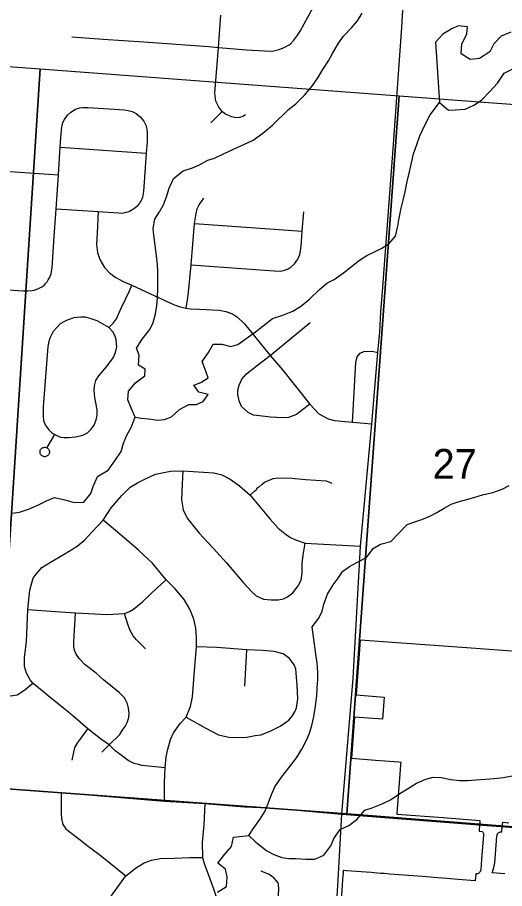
# Model space of a CAD drawing. Extents: x 0 to 34, y 0 to 26.1.
# Drawn here: x 26.652 to 27.339, y 15.919 to 17.147 of the extents above; entities that cross this region are included whole.
import ezdxf

# ---------------------------------------------------------------- set-up
doc = ezdxf.new("R2010")
doc.units = 0
for name, color, linetype in [('GM_X_County_Road', 7, 'Continuous'), ('GM_X_Minor_Lake', 7, 'Continuous'), ('GM_X_Minor_River', 7, 'Continuous'), ('GM_X_Section', 7, 'Continuous'), ('GM_X_Section_Text', 7, 'Continuous'), ('GM_X_Township_Road', 7, 'Continuous'), ('SC_Scratch1', 7, 'Continuous')]:
    doc.layers.add(name, color=color, linetype=linetype)

msp = doc.modelspace()

# ---------------------------------------------------------------- linework, layer by layer
at = {"layer": 'GM_X_County_Road'}
for points in [[(27.0981, 15.8354), (27.1037, 15.9232), (27.1095, 16.024), (27.1253, 16.2152), (27.136, 16.402), (27.1519, 16.5743), (27.1604, 16.6746), (27.1631, 16.7041), (27.1645, 16.7321), (27.1669, 16.7607), (27.1823, 16.9679), (27.1942, 17.1333), (27.1967, 17.1739), (27.2024, 17.2543), (27.2067, 17.3105), (27.2105, 17.3599), (27.2149, 17.4267), (27.2235, 17.5489)], [(25.6593, 16.1329), (25.6738, 16.1311), (25.7938, 16.1231), (25.9933, 16.107), (26.0793, 16.1018), (26.1222, 16.0984), (26.2747, 16.0857), (26.4019, 16.0766), (26.714, 16.0547), (26.8597, 16.0424), (26.9166, 16.0392), (26.9722, 16.0347), (26.9948, 16.0336), (27.0202, 16.032), (27.0574, 16.0287), (27.1095, 16.024), (27.2972, 16.0095), (27.3012, 16.0092)], [(27.3012, 16.0092), (27.3465, 16.0057), (27.3516, 16.0054)]]:
    msp.add_lwpolyline(points, dxfattribs=at)
at = {"layer": 'GM_X_Minor_Lake'}
for points in [[(27.348, 17.1264), (27.3343, 17.1205), (27.3239, 17.1096), (27.3181, 17.0987), (27.3036, 17.0893), (27.2904, 17.0879), (27.2776, 17.0957), (27.2788, 17.1093), (27.2858, 17.1237), (27.2867, 17.1339), (27.2734, 17.1352), (27.2639, 17.1304), (27.2517, 17.1233), (27.2418, 17.112)], [(27.2418, 17.112), (27.2473, 17.0269)], [(27.2473, 17.0269), (27.2597, 17.0165), (27.2695, 17.0168), (27.2835, 17.0178), (27.2957, 17.0234), (27.3064, 17.0305), (27.3183, 17.0425), (27.329, 17.0545), (27.3383, 17.0685), (27.3504, 17.0744)]]:
    msp.add_lwpolyline(points, dxfattribs=at)
at = {"layer": 'GM_X_Minor_River'}
for points in [[(26.9846, 16.9742), (26.9983, 16.9839), (27.0117, 16.9952), (27.0343, 17.0174), (27.0446, 17.0252), (27.0568, 17.0376), (27.0672, 17.0497), (27.0757, 17.0617), (27.083, 17.0734), (27.0907, 17.0858), (27.0965, 17.0964), (27.105, 17.1108), (27.1119, 17.1205), (27.123, 17.1322), (27.1315, 17.1424), (27.138, 17.1529)], [(26.9877, 16.7039), (26.9988, 16.7126), (27.0118, 16.7227), (27.0262, 16.7275), (27.0407, 16.733), (27.0514, 16.7397), (27.064, 16.7498), (27.0781, 16.7637), (27.0885, 16.7723), (27.0987, 16.7779), (27.1117, 16.7873), (27.1232, 16.7959), (27.1346, 16.8049), (27.1446, 16.8116), (27.1548, 16.8164), (27.1659, 16.8216), (27.1758, 16.828), (27.1854, 16.8389), (27.1886, 16.8529), (27.1906, 16.8643), (27.193, 16.8783), (27.1958, 16.8897), (27.1986, 16.9014), (27.2018, 16.9158), (27.2045, 16.9275), (27.2069, 16.9377), (27.2105, 16.9548), (27.2152, 16.968), (27.2195, 16.9801), (27.2265, 16.9952), (27.2342, 17.0096), (27.2473, 17.0269)], [(26.8489, 16.7409), (26.8495, 16.7515), (26.8501, 16.7659), (26.8504, 16.7887), (26.8498, 16.799), (26.8484, 16.8111), (26.8464, 16.8256), (26.8447, 16.84), (26.8437, 16.8495), (26.8461, 16.8628), (26.8523, 16.8729), (26.8582, 16.8831), (26.8625, 16.8941), (26.8661, 16.9062), (26.8723, 16.9201), (26.8857, 16.9309), (26.899, 16.9349), (26.9089, 16.9393), (26.9207, 16.946), (26.9302, 16.9485), (26.9436, 16.9552), (26.9846, 16.9742)], [(26.6442, 16.4484), (26.6552, 16.4498), (26.6693, 16.4545), (26.683, 16.4604), (26.6933, 16.4656), (26.7047, 16.4704), (26.719, 16.4671), (26.7322, 16.4632), (26.7459, 16.4641), (26.7559, 16.4761), (26.759, 16.4859), (26.7653, 16.4999), (26.7802, 16.5088), (26.7894, 16.5223), (26.7983, 16.5355), (26.8019, 16.5468), (26.8066, 16.5585), (26.8128, 16.5691), (26.818, 16.5838), (26.8121, 16.5979), (26.8081, 16.6082), (26.8086, 16.6204), (26.8186, 16.632), (26.832, 16.6417), (26.8325, 16.6512), (26.8228, 16.657), (26.8237, 16.671), (26.8201, 16.6809), (26.8282, 16.6937), (26.839, 16.7073), (26.8437, 16.7171), (26.8469, 16.7295), (26.8489, 16.7409)], [(26.8179, 16.5836), (26.827, 16.5822), (26.8368, 16.5813), (26.8501, 16.5796), (26.8595, 16.5802), (26.8694, 16.5842), (26.8809, 16.5947), (26.8939, 16.6014), (26.9045, 16.6016), (26.914, 16.6056), (26.921, 16.6154), (26.9081, 16.619), (26.9011, 16.6286), (26.9106, 16.6326), (26.9209, 16.6389), (26.9162, 16.6523), (26.9125, 16.6622), (26.9218, 16.675), (26.9284, 16.6867), (26.9405, 16.6865), (26.9533, 16.6833), (26.9628, 16.6862), (26.9877, 16.7039)], [(26.9785, 15.9939), (26.9847, 16.0034), (26.9951, 16.018), (27.0009, 16.0279), (27.0059, 16.0392), (27.0106, 16.0517), (27.0149, 16.0626), (27.0245, 16.0762), (27.0349, 16.0894), (27.0456, 16.1037), (27.0534, 16.1157), (27.0599, 16.1286), (27.0638, 16.1384), (27.0673, 16.149), (27.0694, 16.1596), (27.0718, 16.1732), (27.0742, 16.191), (27.0747, 16.2024), (27.0756, 16.2134), (27.0757, 16.2237), (27.0747, 16.237), (27.073, 16.2499), (27.0695, 16.2742), (27.0677, 16.2883), (27.0769, 16.3003), (27.0816, 16.3101), (27.084, 16.32), (27.0894, 16.334), (27.0975, 16.3472), (27.1044, 16.357), (27.111, 16.3668), (27.1205, 16.3731), (27.1308, 16.3787), (27.1441, 16.3858), (27.1538, 16.3986), (27.164, 16.4045), (27.1785, 16.4086), (27.1896, 16.4198), (27.2015, 16.4322), (27.211, 16.4356), (27.2224, 16.4396), (27.2338, 16.444), (27.2437, 16.4493), (27.2536, 16.4556), (27.2635, 16.4612), (27.2734, 16.4645), (27.284, 16.4674), (27.2958, 16.4703), (27.308, 16.474), (27.3224, 16.4773), (27.3357, 16.4821), (27.3453, 16.4873)], [(26.9785, 15.9939), (26.9883, 15.9847), (27.0037, 15.9724), (27.0135, 15.9674), (27.0248, 15.9631), (27.035, 15.9615), (27.0449, 15.9617), (27.0589, 15.9608), (27.0714, 15.9607), (27.0843, 15.9666), (27.0939, 15.9798), (27.0982, 15.99), (27.1071, 16.0025), (27.1192, 16.0084), (27.1307, 16.0166), (27.1422, 16.0298), (27.1525, 16.0331), (27.1662, 16.0387), (27.1783, 16.0442), (27.1913, 16.0532), (27.202, 16.0599), (27.215, 16.0681), (27.2279, 16.0737), (27.2382, 16.0762), (27.2495, 16.0761), (27.2631, 16.0729), (27.2752, 16.0717), (27.2874, 16.0716), (27.2984, 16.0726), (27.312, 16.0736), (27.3241, 16.0746), (27.3374, 16.076), (27.3499, 16.0781)], [(26.9344, 15.9142), (26.947, 15.9224), (26.948, 15.9353), (26.9455, 15.9467), (26.9346, 15.9552), (26.9447, 15.9676), (26.9539, 15.9788), (26.9567, 15.9917), (26.9785, 15.9939)]]:
    msp.add_lwpolyline(points, dxfattribs=at)
at = {"layer": 'GM_X_Section'}
for points in [[(26.6845, 17.0747), (26.6185, 16.0611), (26.603, 16.0634), (26.1174, 16.097), (26.1914, 17.1109)], [(26.6845, 17.0747), (27.1906, 17.0366), (27.1167, 16.0245), (26.6185, 16.0611)], [(27.1906, 17.0366), (27.6883, 16.9993), (27.6154, 15.9857), (27.1167, 16.0245)], [(26.603, 16.0634), (26.6185, 16.0611), (27.1167, 16.0245), (27.6154, 15.9857), (27.5444, 14.9891), (26.5367, 15.0651)]]:
    msp.add_lwpolyline(points, close=True, dxfattribs=at)
at = {"layer": 'GM_X_Township_Road'}
for p, q in [((26.9248, 16.9986), (26.9407, 17.0142)), ((26.7125, 16.9642), (26.8336, 16.9556)), ((26.902, 16.8567), (27.0536, 16.8457)), ((27.0087, 16.6707), (27.065, 16.7173)), ((26.973, 16.2046), (26.9756, 16.2558))]:
    msp.add_line(p, q, dxfattribs=at)
for points in [[(26.729, 17.1195), (26.7731, 17.1164), (26.8304, 17.1125), (26.9223, 17.1059), (26.9355, 17.1046), (26.9752, 17.1015), (27.0092, 17.0995), (27.0137, 17.0998), (27.0214, 17.1016), (27.0294, 17.105), (27.0352, 17.1084), (27.0376, 17.1104), (27.0418, 17.1148), (27.0473, 17.1223), (27.0506, 17.1275), (27.0564, 17.1381), (27.0769, 17.1762)], [(26.9739, 17.0099), (26.97, 17.0075), (26.9655, 17.0062), (26.9599, 17.0057), (26.9547, 17.0067), (26.9498, 17.0086), (26.9444, 17.0111), (26.9407, 17.0142), (26.9361, 17.0204), (26.9319, 17.029), (26.9304, 17.0404), (26.9355, 17.1046), (26.939, 17.1503)], [(26.7125, 16.9642), (26.7135, 16.9779), (26.715, 16.9929), (26.7164, 16.9989), (26.7184, 17.0031), (26.723, 17.0094), (26.7275, 17.0136), (26.7341, 17.0176), (26.74, 17.0195), (26.7446, 17.0202), (26.7514, 17.0202), (26.8033, 17.0166), (26.8082, 17.0159), (26.8139, 17.0145), (26.8195, 17.0118), (26.8255, 17.007), (26.8303, 17.0008), (26.8332, 16.9953), (26.8347, 16.9893), (26.8352, 16.9834), (26.8349, 16.9718), (26.8336, 16.9556), (26.8301, 16.9018), (26.8297, 16.8987), (26.8291, 16.8961), (26.8284, 16.8936), (26.8274, 16.8911), (26.8266, 16.889), (26.8255, 16.8871), (26.8245, 16.8854), (26.8226, 16.883), (26.8204, 16.8807), (26.8177, 16.8782), (26.815, 16.8763), (26.8128, 16.8749), (26.8104, 16.8737), (26.8078, 16.8727), (26.805, 16.8719), (26.8019, 16.8713), (26.7984, 16.8709), (26.7945, 16.871), (26.766, 16.8729), (26.7067, 16.877)], [(26.6238, 16.764), (26.6606, 16.7619), (26.6668, 16.7617), (26.673, 16.7622), (26.6761, 16.7628), (26.682, 16.7648), (26.6874, 16.7679), (26.6898, 16.7699), (26.692, 16.772), (26.694, 16.7744), (26.6958, 16.777), (26.6973, 16.7798), (26.6985, 16.7826), (26.6996, 16.7856), (26.7013, 16.7947), (26.7041, 16.8383), (26.7067, 16.877), (26.71, 16.9252), (26.7125, 16.9642)], [(26.5768, 16.9233), (26.5883, 16.9277), (26.5994, 16.9312), (26.6086, 16.9317), (26.6286, 16.9306), (26.71, 16.9252)], [(26.8901, 16.7375), (26.893, 16.755), (26.8971, 16.7983), (26.902, 16.8567), (26.904, 16.8707), (26.9058, 16.8771), (26.9086, 16.8828), (26.9148, 16.8924)], [(26.766, 16.8729), (26.7648, 16.8432), (26.7639, 16.827), (26.7651, 16.8155), (26.7684, 16.8057), (26.7751, 16.7947), (26.7824, 16.7867), (26.7908, 16.7804), (26.8014, 16.775), (26.8133, 16.7695), (26.8712, 16.7429), (26.8758, 16.7412), (26.8818, 16.739), (26.8901, 16.7375), (26.8963, 16.7365), (26.9089, 16.7359), (26.9365, 16.7346), (26.9462, 16.7328), (26.9553, 16.7292), (26.9625, 16.7247), (26.9724, 16.7153), (27.0087, 16.6707), (27.0257, 16.6506), (27.0643, 16.6021), (27.077, 16.5884), (27.0902, 16.5814), (27.0992, 16.5789), (27.1244, 16.5766), (27.1519, 16.5743)], [(26.8971, 16.7983), (27.0141, 16.7897), (27.0226, 16.7895), (27.0271, 16.7905), (27.0339, 16.7925), (27.0383, 16.7956), (27.0427, 16.7996), (27.0476, 16.8065), (27.0504, 16.8128), (27.0517, 16.8208), (27.0525, 16.8307), (27.0536, 16.8457), (27.0558, 16.8732)], [(26.7812, 16.7102), (26.7875, 16.7167), (26.7918, 16.7223), (26.7949, 16.7289), (26.7991, 16.7382), (26.81, 16.7618), (26.8133, 16.7695)], [(26.7812, 16.7102), (26.7648, 16.7192), (26.7546, 16.7229), (26.7477, 16.7245), (26.7415, 16.7248), (26.7365, 16.7241), (26.7315, 16.7235), (26.7265, 16.722), (26.7225, 16.7204), (26.7185, 16.7184), (26.7125, 16.7151), (26.7076, 16.7101), (26.7026, 16.7042), (26.6979, 16.6952), (26.6964, 16.6905), (26.6951, 16.6834), (26.6886, 16.5981), (26.6883, 16.5857), (26.6889, 16.5791), (26.6914, 16.5729), (26.6964, 16.5658), (26.7008, 16.5615), (26.705, 16.5591), (26.7076, 16.5577), (26.7105, 16.5566), (26.7135, 16.5557), (26.7179, 16.5548), (26.7241, 16.5549), (26.7348, 16.5559), (26.7443, 16.5583), (26.7511, 16.5617), (26.7563, 16.5667), (26.7605, 16.5723), (26.7633, 16.5801), (26.7648, 16.5863), (26.7645, 16.5938), (26.7614, 16.6115), (26.7605, 16.6215), (26.7608, 16.628), (26.763, 16.6355), (26.767, 16.642), (26.7779, 16.6547), (26.7872, 16.6672), (26.7906, 16.6747), (26.7925, 16.6828), (26.7916, 16.693), (26.7897, 16.6989), (26.7866, 16.7039), (26.7812, 16.7102)], [(27.1244, 16.5766), (27.1294, 16.6606), (27.1312, 16.6686), (27.1354, 16.6738), (27.1406, 16.6762), (27.1522, 16.6766), (27.1604, 16.6746)], [(27.0643, 16.6021), (27.0458, 16.5873), (27.0345, 16.5833), (27.0259, 16.5825), (27.0088, 16.5837), (26.9936, 16.5854), (26.9852, 16.5865), (26.9773, 16.5903), (26.9679, 16.5989), (26.9647, 16.6066), (26.9628, 16.6155), (26.9628, 16.6216), (26.9646, 16.6286), (26.9684, 16.6374), (26.9752, 16.6447), (26.9906, 16.6568), (27.0087, 16.6707)], [(26.694, 16.5403), (26.6948, 16.5398), (26.6956, 16.539), (26.6963, 16.5381), (26.6968, 16.5371), (26.6971, 16.536), (26.6973, 16.5349), (26.6973, 16.5338), (26.697, 16.5327), (26.6966, 16.5316), (26.696, 16.5307), (26.6953, 16.5298), (26.6944, 16.5291), (26.6934, 16.5286), (26.6924, 16.5282), (26.6913, 16.528), (26.6901, 16.528), (26.689, 16.5282), (26.688, 16.5286), (26.687, 16.5291), (26.6861, 16.5298), (26.6853, 16.5307), (26.6848, 16.5316), (26.6843, 16.5327), (26.6841, 16.5338), (26.6841, 16.5349), (26.6842, 16.536), (26.6845, 16.5371), (26.685, 16.5381), (26.6857, 16.539), (26.6865, 16.5398), (26.6875, 16.5404), (26.6885, 16.5409), (26.6896, 16.5411), (26.6907, 16.5412), (26.6916, 16.5412), (26.6924, 16.541), (26.6932, 16.5407), (26.694, 16.5409), (26.705, 16.5591)], [(26.8603, 16.0896), (26.8325, 16.0922), (26.8275, 16.093), (26.8228, 16.0942), (26.817, 16.0955), (26.8084, 16.0997), (26.8002, 16.1057), (26.7902, 16.1136), (26.7814, 16.1218), (26.7694, 16.1305), (26.7515, 16.1444), (26.7337, 16.1599), (26.7245, 16.1675), (26.6954, 16.191), (26.674, 16.2087), (26.6702, 16.2134), (26.6652, 16.2229), (26.6624, 16.2321), (26.6624, 16.2452), (26.6649, 16.2672), (26.6669, 16.3126), (26.6696, 16.3398), (26.6725, 16.3502), (26.6744, 16.357), (26.6786, 16.3626), (26.6867, 16.3716), (26.6987, 16.3791), (26.7182, 16.3908), (26.7364, 16.4021), (26.7474, 16.4109), (26.7574, 16.4219), (26.7731, 16.4383), (26.7845, 16.4557), (26.7995, 16.4732), (26.8113, 16.485), (26.8215, 16.4911), (26.8329, 16.4968), (26.8467, 16.5033), (26.8678, 16.5074), (26.8852, 16.5079), (26.9146, 16.5062), (26.9292, 16.5054), (26.9402, 16.5025), (26.952, 16.4964), (26.9654, 16.4871), (26.9805, 16.4736), (26.9967, 16.4541), (27.0085, 16.4399), (27.0199, 16.4273), (27.0293, 16.4195), (27.0362, 16.4147), (27.0443, 16.4106), (27.0577, 16.4061), (27.136, 16.402)], [(26.8852, 16.5079), (26.8845, 16.4891), (26.8837, 16.4671), (26.8857, 16.4533), (26.8914, 16.4415), (26.9085, 16.4204), (26.9284, 16.3992), (26.9471, 16.3785), (26.9711, 16.35), (26.9821, 16.3378), (26.989, 16.3321), (26.9992, 16.3272), (27.0098, 16.3264), (27.0199, 16.3264), (27.0272, 16.3276), (27.0329, 16.3304), (27.0403, 16.3361), (27.048, 16.3459), (27.052, 16.354), (27.0537, 16.3638), (27.0537, 16.3776), (27.0549, 16.3894), (27.0577, 16.4061)], [(26.9805, 16.4736), (26.9868, 16.4799), (26.9883, 16.481), (26.9896, 16.4821), (26.9913, 16.4844), (26.9928, 16.4855), (26.9973, 16.4894), (27.0004, 16.492), (27.0126, 16.4972), (27.0195, 16.4981), (27.0393, 16.4976), (27.0582, 16.4957), (27.0874, 16.494), (27.0955, 16.4905)], [(26.8374, 16.3828), (26.8231, 16.3963), (26.7994, 16.4166), (26.7731, 16.4383)], [(26.8597, 16.0424), (26.8594, 16.0683), (26.86, 16.0802), (26.8603, 16.0896), (26.862, 16.1048), (26.8643, 16.1156), (26.8678, 16.1293), (26.8724, 16.1388), (26.8816, 16.152), (26.8899, 16.161), (26.8961, 16.1759), (26.8992, 16.1897), (26.9018, 16.2261), (26.9032, 16.2438), (26.9047, 16.2601), (26.9049, 16.273), (26.9036, 16.2861), (26.901, 16.2988), (26.8953, 16.3132), (26.8872, 16.3265), (26.8746, 16.3418), (26.8621, 16.3543), (26.8422, 16.3783), (26.8374, 16.3828)], [(26.6669, 16.3126), (26.7059, 16.3099), (26.7341, 16.3081), (26.7608, 16.3067), (26.7785, 16.3055), (26.8032, 16.3069), (26.8069, 16.3084), (26.8101, 16.3097), (26.8161, 16.3131), (26.8285, 16.3233), (26.8496, 16.3435), (26.8621, 16.3543)], [(26.7713, 16.1117), (26.7814, 16.1218), (26.7964, 16.1363), (26.8001, 16.1419), (26.8043, 16.1478), (26.8071, 16.1536), (26.8094, 16.1604), (26.8099, 16.1664), (26.8086, 16.1738), (26.8073, 16.1795), (26.8033, 16.1881), (26.796, 16.1952), (26.7856, 16.2038), (26.7735, 16.2135), (26.7631, 16.2228), (26.7476, 16.2347), (26.7391, 16.2437), (26.7352, 16.2496), (26.7328, 16.2552), (26.7319, 16.2601), (26.7317, 16.2664), (26.7328, 16.2836), (26.7341, 16.3081)], [(26.833, 16.2574), (26.8264, 16.2636), (26.82, 16.27), (26.8152, 16.2757), (26.8105, 16.2838), (26.8073, 16.2932), (26.8032, 16.3069)], [(26.8899, 16.161), (26.9167, 16.1458), (26.9358, 16.1362), (26.9502, 16.1328), (26.9602, 16.1322), (26.9755, 16.1329), (26.9874, 16.135), (26.9955, 16.1362), (27.0087, 16.141), (27.0225, 16.1483), (27.0347, 16.1565), (27.0394, 16.1624), (27.0434, 16.1686), (27.0456, 16.1742), (27.0473, 16.1866), (27.0468, 16.2058), (27.0448, 16.2291), (27.0423, 16.2345), (27.0358, 16.2438), (27.027, 16.25), (27.0144, 16.2534), (26.9975, 16.2548), (26.9756, 16.2558), (26.9333, 16.2593), (26.9047, 16.2601)], [(26.528, 16.2353), (26.5458, 16.2137), (26.5551, 16.2052), (26.5687, 16.1973), (26.5873, 16.1928), (26.6077, 16.1922), (26.643, 16.191), (26.6519, 16.1926), (26.6571, 16.1957), (26.6631, 16.1998), (26.674, 16.2087)], [(26.7294, 16.1003), (26.7331, 16.1181), (26.7374, 16.1251), (26.7432, 16.1325), (26.7515, 16.1444)], [(26.714, 16.0547), (26.7138, 16.0409), (26.714, 16.0355), (26.7138, 16.0254), (26.7145, 16.0178), (26.7163, 16.0096), (26.7203, 16.0035), (26.7272, 15.9982), (26.7386, 15.9895), (26.75, 15.9807), (26.7708, 15.9651), (26.805, 15.9374)], [(26.9166, 16.0392), (26.9148, 16.0092), (26.9126, 15.9845), (26.913, 15.963), (26.9157, 15.9549), (26.9229, 15.9347), (26.9282, 15.9204), (26.9345, 15.902), (26.9373, 15.8827), (26.9408, 15.863), (26.9417, 15.845), (26.9407, 15.8223), (26.9385, 15.7878), (26.9359, 15.7603), (26.935, 15.7379), (26.9346, 15.7242), (26.9366, 15.7162), (26.9395, 15.709), (26.9446, 15.7023), (26.9592, 15.6879), (26.9677, 15.6866), (27.0047, 15.6842), (27.0293, 15.6814), (27.0868, 15.6765)], [(26.5845, 15.7895), (26.6236, 15.7878), (26.6445, 15.7859), (26.66, 15.7853), (26.6757, 15.7875), (26.6932, 15.7935), (26.7073, 15.7995), (26.7199, 15.8112), (26.7293, 15.8196), (26.7433, 15.8401), (26.7597, 15.8691), (26.7831, 15.9066), (26.805, 15.9374), (26.82, 15.9491), (26.8309, 15.9557), (26.8414, 15.9592), (26.8536, 15.9618), (26.8734, 15.9624), (26.8955, 15.963), (26.913, 15.963)], [(26.9407, 15.8223), (26.9871, 15.8217), (26.996, 15.8252), (27.0052, 15.8309), (27.0105, 15.8373), (27.0157, 15.8474), (27.019, 15.8672), (27.0199, 15.906), (27.0209, 15.9182), (27.0205, 15.925), (27.0197, 15.9276), (27.0172, 15.9307), (27.0138, 15.9347), (27.0071, 15.9394), (26.9958, 15.9438)]]:
    msp.add_lwpolyline(points, dxfattribs=at)
at = {"layer": 'SC_Scratch1'}
for points in [[(27.3809, 16.2514), (27.292, 16.258), (27.1356, 16.2696), (27.1297, 16.1922), (27.1694, 16.1892), (27.167, 16.1581), (27.1274, 16.161), (27.123, 16.103), (27.1571, 16.1004), (27.1897, 16.0979), (27.1925, 16.0977), (27.1922, 16.0938), (27.1912, 16.0807), (27.1875, 16.0315), (27.1869, 16.0243), (27.2522, 16.0193), (27.3042, 16.0152), (27.3039, 16.0112), (27.3037, 16.0096), (27.303, 16.0001), (27.3076, 15.9998), (27.3082, 15.9989), (27.3087, 15.998), (27.3091, 15.997), (27.3092, 15.996), (27.3092, 15.9949), (27.3066, 15.9608), (27.3054, 15.9459), (27.3052, 15.9448), (27.3048, 15.9437), (27.3043, 15.9427), (27.3035, 15.9418), (27.3027, 15.9411), (27.3017, 15.9405), (27.3006, 15.9401), (27.2994, 15.9399), (27.2983, 15.9399), (27.2975, 15.9304), (27.2735, 15.9323), (27.2578, 15.9335), (27.2386, 15.935), (27.235, 15.9353), (27.2168, 15.9367), (27.2036, 15.9377), (27.1904, 15.9388), (27.1772, 15.9398), (27.1693, 15.9404), (27.164, 15.9408), (27.1508, 15.9419), (27.1162, 15.9445), (27.1115, 15.9449), (27.1112, 15.9403), (27.111, 15.9377), (27.1101, 15.9245), (27.1084, 15.9015)], [(27.3391, 15.94), (27.3217, 15.9414), (27.3232, 15.9473), (27.3252, 15.9557), (27.3271, 15.9807), (27.3281, 15.9934), (27.3283, 15.9945), (27.3286, 15.9955), (27.3291, 15.9964), (27.3297, 15.9973), (27.3305, 15.998), (27.3313, 15.9986), (27.3322, 15.999), (27.3332, 15.9994), (27.3342, 15.9995), (27.3352, 15.9995), (27.3358, 16.0071), (27.336, 16.0098), (27.3363, 16.0127), (27.3448, 16.0121)]]:
    msp.add_lwpolyline(points, dxfattribs=at)

# ---------------------------------------------------------------- texts
at = {"layer": 'GM_X_Section_Text'}
msp.add_text('27', height=0.04186, rotation=0, dxfattribs=at).set_placement((27.2375, 16.4969))

doc.saveas('drawing.dxf')
